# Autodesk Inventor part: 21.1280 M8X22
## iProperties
Created: 2006-02
Part Number: 21.1280 M8X22
Material: Steel, Mild
Description: Cylinder Head Cap Screw
Document SubType Name: Modeling
Standard: DIN 7984
Designer: Andy Moles
Standards Organization: DIN
Language: en-US
Size Designation: M8 x 20
Categories: <MemberInstance><Categories><Category DisplayName="Fasteners" InternalName="e4da775c-781d-43d5-af7c-5136215cf5a6" Mnemonic="FSTN"><Category DisplayName="Bolts"
Density: 7.86 g/cm^3
Mass: 13.0532 g
Surface Area: 10.6794 cm^2
Volume: 1.66071 cm^3
Author: Andy Moles
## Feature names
1. Body [Revolution]
2. Slot [Extrusion]
3. Fillet1
4. Chamfer1
